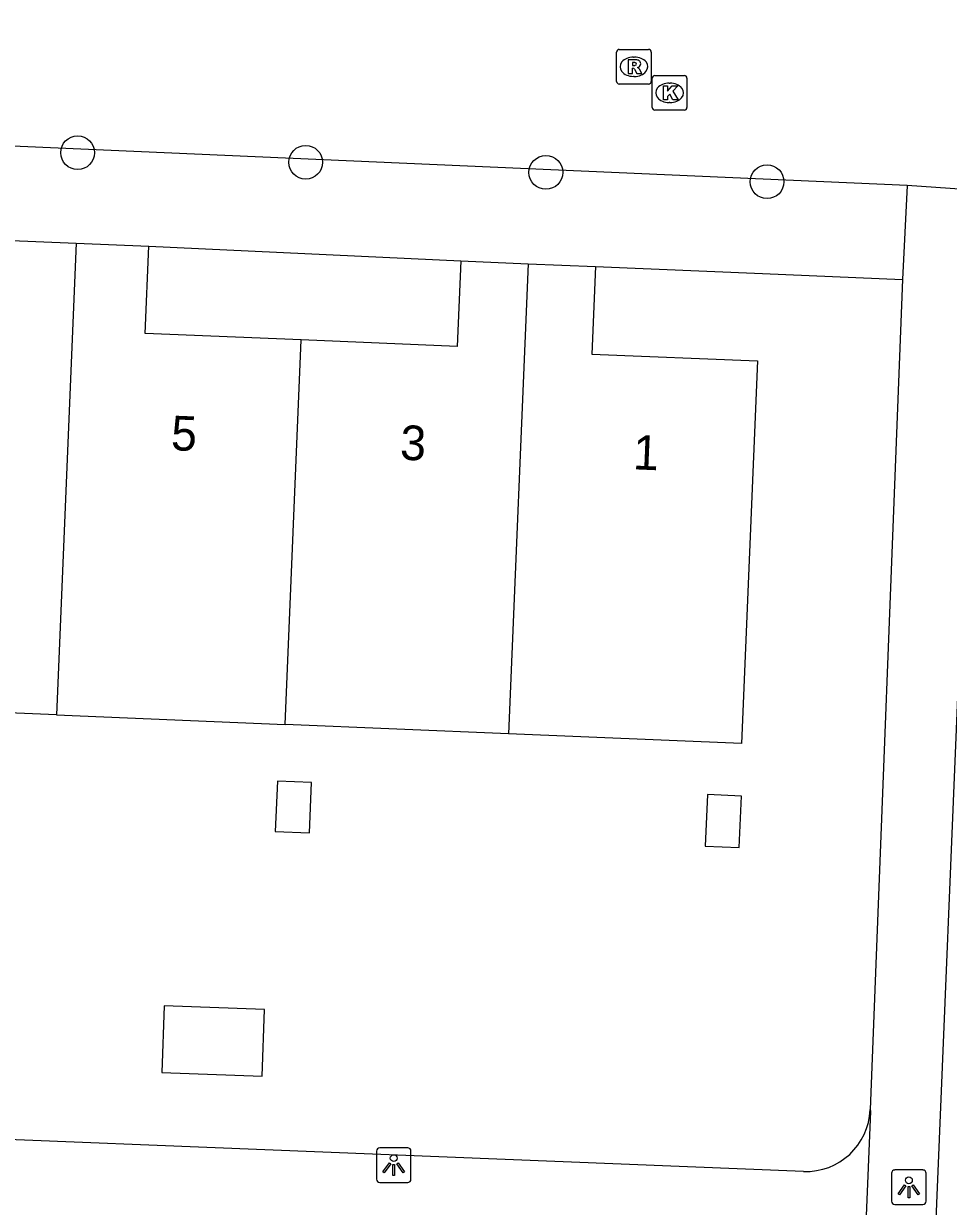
# Model space of a CAD drawing. Extents: x 160787 to 161428, y 386828 to 387483.
# Drawn here: x 161266.19 to 161292.92, y 386954.42 to 386988.62 of the extents above; entities that cross this region are included whole.
import ezdxf

# ---------------------------------------------------------------- set-up
doc = ezdxf.new("R2010")
doc.units = 0
for name, color, linetype in [('IMGEO_Boom', 7, 'Continuous'), ('IMGEO_Kolk', 7, 'Continuous'), ('IMGEO_Lichtpunt', 7, 'Continuous'), ('IMGEO_Pand', 7, 'Continuous'), ('IMGEO_Pand_nummerreeks', 7, 'Continuous'), ('IMGEO_Parkeervlak_open', 7, 'Continuous'), ('IMGEO_Rijbaan_lokaal_gesloten', 7, 'Continuous'), ('IMGEO_Rijbaan_lokaal_open', 7, 'Continuous'), ('IMGEO_Rioolput', 7, 'Continuous'), ('IMGEO_Voetpad_open', 7, 'Continuous')]:
    doc.layers.add(name, color=color, linetype=linetype)

msp = doc.modelspace()

# ---------------------------------------------------------------- linework, layer by layer
at = {"layer": 'IMGEO_Boom'}
for centre in [(161267.747, 386984.888), (161274.341, 386984.61), (161281.285, 386984.318), (161287.679, 386984.048)]:
    msp.add_circle(centre, 0.489, dxfattribs=at)
at = {"layer": 'IMGEO_Kolk'}
for p, q in [((161284.361, 386986.193), (161284.361, 386987.045)), ((161284.436, 386987.119), (161285.288, 386987.119)), ((161285.362, 386987.045), (161285.362, 386986.193)), ((161284.849, 386986.899), (161284.874, 386986.899)), ((161284.872, 386986.339), (161284.847, 386986.339)), ((161285.288, 386986.119), (161284.436, 386986.119))]:
    msp.add_line(p, q, dxfattribs=at)
for points in [[(161284.361, 386986.193), (161284.361, 386987.045)], [(161284.436, 386987.119), (161285.288, 386987.119)], [(161285.362, 386987.045), (161285.362, 386986.193)], [(161284.682, 386986.819), (161284.805, 386986.819), (161284.805, 386986.668), (161284.935, 386986.819), (161285.099, 386986.819), (161284.953, 386986.668), (161285.106, 386986.419), (161284.954, 386986.419), (161284.869, 386986.583), (161284.805, 386986.516), (161284.805, 386986.419), (161284.682, 386986.419), (161284.682, 386986.819)], [(161285.288, 386986.119), (161284.436, 386986.119)]]:
    msp.add_lwpolyline(points, dxfattribs=at)
for centre, start, end in [((161284.438, 386987.043), 91.552, 178.448), ((161284.438, 386987.043), 91.552, 178.448), ((161285.286, 386987.043), 1.552, 88.448), ((161285.286, 386987.043), 1.552, 88.448), ((161284.438, 386986.195), 181.552, 268.448), ((161284.438, 386986.195), 181.552, 268.448), ((161285.286, 386986.195), 271.552, 358.448), ((161285.286, 386986.195), 271.552, 358.448)]:
    msp.add_arc(centre, 0.0765, start, end, dxfattribs=at)
for centre, major_axis, ratio, start_param, end_param in [((161284.848, 386986.619), (-0.387, 0.002), 0.722429, 4.712389, 7.853982), ((161284.873, 386986.619), (-0.39, 0.002), 0.717154, 1.570796, 4.712389)]:
    msp.add_ellipse(centre, major_axis=major_axis, ratio=ratio, start_param=start_param, end_param=end_param, dxfattribs=at)
at = {"layer": 'IMGEO_Lichtpunt'}
for p, q in [((161276.388, 386956.018), (161276.388, 386955.211)), ((161276.388, 386956.018), (161276.388, 386955.211)), ((161277.29, 386956.113), (161276.482, 386956.113)), ((161277.29, 386956.113), (161276.482, 386956.113)), ((161277.384, 386955.211), (161277.384, 386956.018)), ((161277.384, 386955.211), (161277.384, 386956.018)), ((161291.28, 386955.379), (161291.28, 386954.572)), ((161291.28, 386955.379), (161291.28, 386954.572)), ((161292.182, 386955.474), (161291.374, 386955.474)), ((161292.182, 386955.474), (161291.374, 386955.474)), ((161292.276, 386954.572), (161292.276, 386955.379)), ((161292.276, 386954.572), (161292.276, 386955.379)), ((161276.482, 386955.117), (161277.29, 386955.117)), ((161276.482, 386955.117), (161277.29, 386955.117)), ((161291.374, 386954.478), (161292.182, 386954.478)), ((161291.374, 386954.478), (161292.182, 386954.478))]:
    msp.add_line(p, q, dxfattribs=at)
for points in [[(161276.762, 386955.682), (161276.801, 386955.654), (161276.613, 386955.392), (161276.575, 386955.419), (161276.762, 386955.682)], [(161276.864, 386955.634), (161276.911, 386955.634), (161276.911, 386955.312), (161276.864, 386955.312), (161276.864, 386955.634)], [(161276.974, 386955.654), (161277.012, 386955.681), (161277.199, 386955.419), (161277.16, 386955.391), (161276.974, 386955.654)], [(161291.654, 386955.043), (161291.693, 386955.015), (161291.505, 386954.753), (161291.467, 386954.78), (161291.654, 386955.043)], [(161291.756, 386954.995), (161291.803, 386954.995), (161291.803, 386954.673), (161291.756, 386954.673), (161291.756, 386954.995)], [(161291.866, 386955.015), (161291.904, 386955.042), (161292.091, 386954.78), (161292.052, 386954.752), (161291.866, 386955.015)]]:
    msp.add_lwpolyline(points, dxfattribs=at)
for centre in [(161276.887, 386955.816), (161291.779, 386955.177)]:
    msp.add_circle(centre, 0.0994, dxfattribs=at)
for centre, start, end in [((161276.482, 386956.018), 90, 180), ((161276.482, 386956.018), 90, 180), ((161277.29, 386956.018), 0, 90), ((161277.29, 386956.018), 0, 90), ((161276.482, 386955.211), 180, 270), ((161276.482, 386955.211), 180, 270), ((161277.29, 386955.211), 270, 0), ((161277.29, 386955.211), 270, 360), ((161291.374, 386955.379), 90, 180), ((161291.374, 386955.379), 90, 180), ((161292.182, 386955.379), 0, 90), ((161292.182, 386955.379), 0, 90), ((161291.374, 386954.572), 180, 270), ((161291.374, 386954.572), 180, 270), ((161292.182, 386954.572), 270, 0), ((161292.182, 386954.572), 270, 360)]:
    msp.add_arc(centre, 0.0946, start, end, dxfattribs=at)
at = {"layer": 'IMGEO_Pand'}
for points in [[(161265.606, 386982.361), (161267.708, 386982.273)], [(161267.708, 386982.273), (161267.14, 386968.631)], [(161267.708, 386982.273), (161269.809, 386982.186)], [(161274.212, 386979.473), (161269.704, 386979.661), (161269.809, 386982.186)], [(161278.822, 386981.757), (161278.719, 386979.285), (161274.212, 386979.473)], [(161278.822, 386981.757), (161280.77, 386981.676)], [(161280.77, 386981.676), (161280.204, 386968.086)], [(161282.721, 386981.594), (161282.616, 386979.067), (161287.399, 386978.868), (161286.937, 386967.806), (161280.204, 386968.086)], [(161280.77, 386981.676), (161282.721, 386981.594)], [(161273.749, 386968.355), (161274.212, 386979.473)], [(161267.14, 386968.631), (161260.416, 386968.911)], [(161267.14, 386968.631), (161273.749, 386968.355)], [(161280.204, 386968.086), (161273.749, 386968.355)], [(161273.46, 386965.261), (161274.45, 386965.219), (161274.511, 386966.679), (161273.521, 386966.721), (161273.46, 386965.261)], [(161285.891, 386964.838), (161286.875, 386964.796), (161286.939, 386966.287), (161285.954, 386966.328), (161285.891, 386964.838)], [(161270.179, 386958.291), (161273.078, 386958.185), (161273.148, 386960.112), (161270.249, 386960.217), (161270.179, 386958.291)]]:
    msp.add_lwpolyline(points, dxfattribs=at)
at = {"layer": 'IMGEO_Parkeervlak_open'}
for points in [[(161269.809, 386982.186), (161278.822, 386981.757)], [(161282.721, 386981.594), (161287.546, 386981.393), (161291.591, 386981.225)]]:
    msp.add_lwpolyline(points, dxfattribs=at)
at = {"layer": 'IMGEO_Rijbaan_lokaal_gesloten'}
msp.add_lwpolyline([(161288.788, 386902.201), (161289.271, 386902.937), (161289.686, 386903.713), (161290.03, 386904.523), (161290.3, 386905.361), (161290.494, 386906.22), (161290.611, 386907.092), (161290.641, 386907.552), (161293.806, 386983.797)], dxfattribs=at)
at = {"layer": 'IMGEO_Rijbaan_lokaal_open'}
for points in [[(161291.727, 386983.944), (161185.206, 386988.619)], [(161293.806, 386983.797), (161291.727, 386983.944)]]:
    msp.add_lwpolyline(points, dxfattribs=at)
at = {"layer": 'IMGEO_Rioolput'}
for p, q in [((161283.329, 386986.947), (161283.329, 386987.799)), ((161283.404, 386987.873), (161284.256, 386987.873)), ((161284.33, 386987.799), (161284.33, 386986.947)), ((161283.817, 386987.653), (161283.842, 386987.653)), ((161283.84, 386987.093), (161283.815, 386987.093)), ((161284.256, 386986.873), (161283.404, 386986.873))]:
    msp.add_line(p, q, dxfattribs=at)
for points in [[(161283.329, 386986.947), (161283.329, 386987.799)], [(161283.404, 386987.873), (161284.256, 386987.873)], [(161284.33, 386987.799), (161284.33, 386986.947)], [(161283.918, 386987.571), (161283.666, 386987.573), (161283.666, 386987.173)], [(161283.844, 386987.492), (161283.79, 386987.492), (161283.79, 386987.411)], [(161283.79, 386987.411), (161283.842, 386987.411)], [(161283.666, 386987.173), (161283.79, 386987.173), (161283.79, 386987.335), (161283.801, 386987.335)], [(161283.848, 386987.306), (161283.919, 386987.173), (161284.059, 386987.173), (161283.994, 386987.299)], [(161284.256, 386986.873), (161283.404, 386986.873)]]:
    msp.add_lwpolyline(points, dxfattribs=at)
for centre, radius, start, end in [((161283.406, 386987.797), 0.0765, 91.552, 178.448), ((161283.406, 386987.797), 0.0765, 91.552, 178.448), ((161284.254, 386987.797), 0.0765, 1.552, 88.448), ((161284.254, 386987.797), 0.0765, 1.552, 88.448), ((161283.826, 386987.6), 0.19, 274.7715, 282.9687), ((161283.85, 386987.396), 0.0964, 77.0061, 93.1865), ((161283.864, 386987.453), 0.0378, 276.6634, 79.6772), ((161283.917, 386987.461), 0.109, 350.3612, 89.416), ((161283.915, 386987.461), 0.112, 277.5842, 350.9817), ((161283.899, 386987.246), 0.108, 29.5134, 73.7905), ((161283.8, 386987.282), 0.0533, 26.0293, 88.6989), ((161283.406, 386986.949), 0.0765, 181.552, 268.448), ((161283.406, 386986.949), 0.0765, 181.552, 268.448), ((161284.254, 386986.949), 0.0765, 271.552, 358.448), ((161284.254, 386986.949), 0.0765, 271.552, 358.448)]:
    msp.add_arc(centre, radius, start, end, dxfattribs=at)
for centre, major_axis, ratio, start_param, end_param in [((161283.816, 386987.373), (-0.387, 0.002), 0.722429, 4.712389, 7.853982), ((161283.841, 386987.373), (-0.39, 0.002), 0.717154, 1.570796, 4.712389)]:
    msp.add_ellipse(centre, major_axis=major_axis, ratio=ratio, start_param=start_param, end_param=end_param, dxfattribs=at)
at = {"layer": 'IMGEO_Voetpad_open'}
for points in [[(161291.727, 386983.944), (161291.591, 386981.225)], [(161291.591, 386981.225), (161290.663, 386957.219)], [(161288.733, 386955.432), (161248.948, 386957.027)], [(161290.663, 386957.219), (161290.668, 386957.173), (161290.386, 386950.426)]]:
    msp.add_lwpolyline(points, dxfattribs=at)
msp.add_arc((161288.804, 386957.291), 1.86, 267.8136, 357.78, dxfattribs=at)

# ---------------------------------------------------------------- texts
at = {"layer": 'IMGEO_Pand_nummerreeks'}
for s, p in [('5', (161270.435, 386976.289)), ('3', (161277.057, 386976.014)), ('1', (161283.791, 386975.735))]:
    msp.add_text(s, height=1, rotation=357.6246, dxfattribs=at).set_placement(p)

doc.saveas('drawing.dxf')
